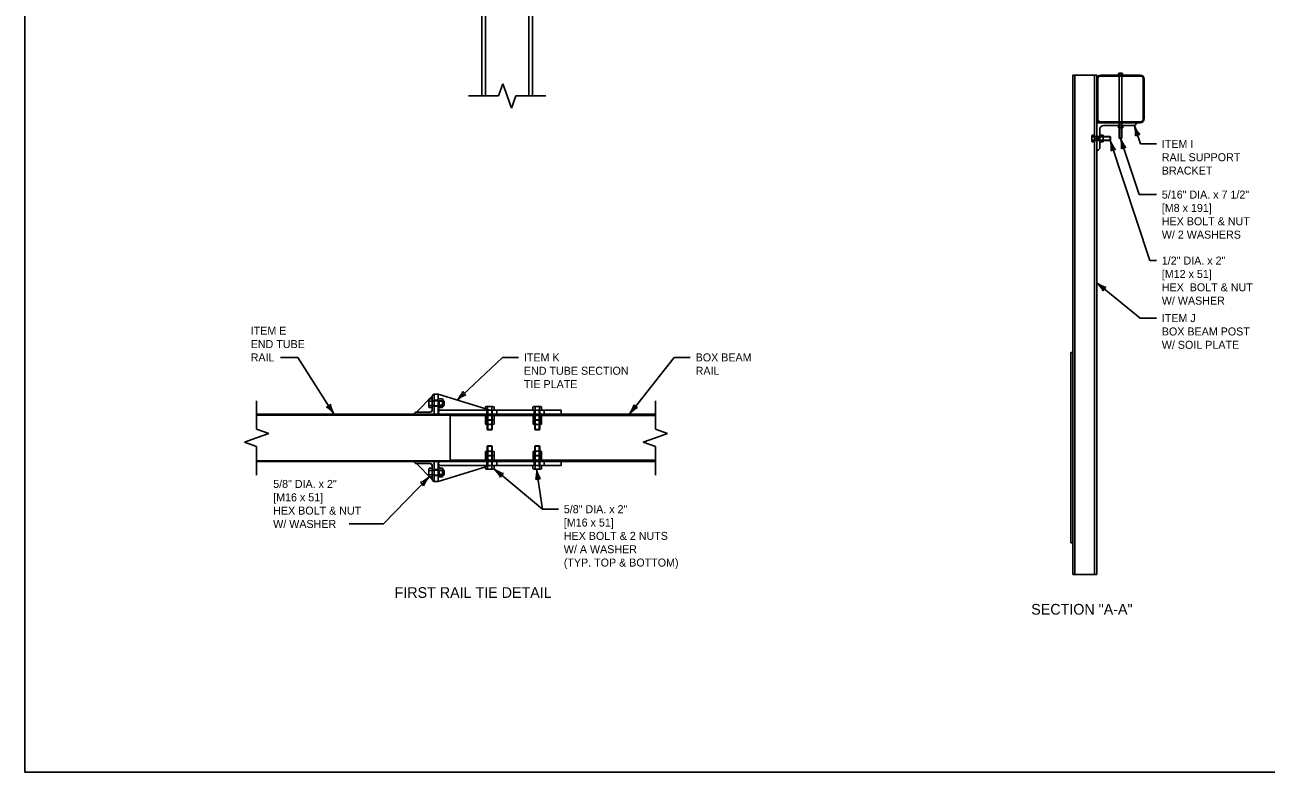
# Model space of a CAD drawing. Extents: x 49991.4 to 50021, y 49987.6 to 50011.4.
# Drawn here: x 49999.38 to 50008.69, y 49987.8 to 49993.4 of the extents above; entities that cross this region are included whole.
import ezdxf

# ---------------------------------------------------------------- set-up
doc = ezdxf.new("R2010")
doc.units = 0
for name, color, linetype in [('Level 1', 7, 'Continuous'), ('Level 2', 7, 'Continuous'), ('Level 3', 7, 'Continuous'), ('Level 4', 7, 'Continuous'), ('Level 6', 7, 'Continuous'), ('Level 63', 7, 'Continuous')]:
    doc.layers.add(name, color=color, linetype=linetype)

# ---------------------------------------------------------------- blocks, each defined once
blk = doc.blocks.new('HEX$NU')
at = {"layer": 'Level 63'}
for p, q in [((0, -0.32), (0, 0.32)), ((0.03, 0.43), (0.42, 0.43)), ((0.03, 0.22), (0.42, 0.22)), ((0.45, 0.32), (0.45, -0.32)), ((0.03, -0.22), (0.42, -0.22)), ((0.42, -0.43), (0.03, -0.43))]:
    blk.add_line(p, q, dxfattribs=at)
for centre, radius, start, end in [((0.21, 0.32), 0.21, 149.0201, 210.9799), ((0.8, 0), 0.796, 164.2217, 195.7782), ((0.24, 0.32), 0.21, 329.0201, 30.9799), ((-0.35, 0), 0.796, 344.2218, 15.7783), ((0.21, -0.32), 0.21, 149.0201, 210.9799), ((0.24, -0.32), 0.21, 329.0201, 30.9799)]:
    blk.add_arc(centre, radius, start, end, dxfattribs=at)

msp = doc.modelspace()

# ---------------------------------------------------------------- linework, layer by layer
at = {"layer": 'Level 1'}
for p, q in [((50003.1884, 49995.2856), (50003.1884, 49992.8668)), ((50002.8094, 49995.1742), (50002.8094, 49992.8668)), ((50002.8364, 49995.1742), (50002.8364, 49992.8668)), ((50003.1614, 49995.1742), (50003.1614, 49992.8668)), ((50007.241, 49993.0223), (50007.4192, 49993.0223)), ((50007.241, 49993.0223), (50007.241, 49990.9431)), ((50007.2564, 49993.0223), (50007.2564, 49989.2797)), ((50007.4038, 49993.0223), (50007.4038, 49989.2797)), ((50007.4192, 49993.0223), (50007.4192, 49989.2797)), ((50007.7459, 49993.0223), (50007.4489, 49993.0223)), ((50007.5854, 49993.0358), (50007.6095, 49993.0358)), ((50007.5894, 49993.0345), (50007.5894, 49993.0223)), ((50007.6055, 49993.0345), (50007.6055, 49993.0223)), ((50007.4266, 49992.9926), (50007.4266, 49992.6956)), ((50007.7459, 49993.0149), (50007.4489, 49993.0149)), ((50007.7682, 49992.6956), (50007.7682, 49992.9926)), ((50007.7756, 49992.6956), (50007.7756, 49992.9926)), ((50007.4192, 49992.6659), (50007.7162, 49992.6659)), ((50007.4489, 49992.6733), (50007.7459, 49992.6733)), ((50007.4489, 49992.6659), (50007.7459, 49992.6659)), ((50007.6067, 49992.6659), (50007.5881, 49992.6659)), ((50007.3821, 49992.5278), (50007.3821, 49992.5663)), ((50007.3842, 49992.5599), (50007.4038, 49992.5599)), ((50007.4415, 49992.6139), (50007.4415, 49992.4728)), ((50007.5196, 49992.5619), (50007.4681, 49992.5619)), ((50007.7014, 49992.6436), (50007.4712, 49992.6436)), ((50007.5196, 49992.5322), (50007.5196, 49992.5619)), ((50007.5196, 49992.5619), (50007.5226, 49992.5589)), ((50007.5226, 49992.5589), (50007.5226, 49992.5352)), ((50007.5881, 49992.5489), (50007.5881, 49992.6269)), ((50007.6067, 49992.6269), (50007.6067, 49992.5489)), ((50007.3842, 49992.5342), (50007.4038, 49992.5342)), ((50007.5196, 49992.5322), (50007.4681, 49992.5322)), ((50007.5196, 49992.5322), (50007.5226, 49992.5352)), ((50007.5881, 49992.5489), (50007.59, 49992.547)), ((50007.5881, 49992.5489), (50007.6067, 49992.5489)), ((50007.6049, 49992.547), (50007.59, 49992.547)), ((50007.6067, 49992.5489), (50007.6049, 49992.547)), ((50007.2261, 49990.9431), (50007.241, 49990.9431)), ((50007.2261, 49990.9431), (50007.2261, 49989.5173)), ((50007.241, 49990.9431), (50007.241, 49989.5173)), ((50002.4381, 49990.6157), (50002.3193, 49990.4969)), ((50002.4381, 49990.6157), (50002.4381, 49990.5117)), ((50002.453, 49990.482), (50002.453, 49990.6305)), ((50002.453, 49990.6305), (50002.4827, 49990.6305)), ((50002.4827, 49990.6305), (50002.4827, 49990.482)), ((50002.4827, 49990.6305), (50002.8725, 49990.5117)), ((50002.4111, 49990.5878), (50002.4111, 49990.5396)), ((50002.4137, 49990.5798), (50002.4381, 49990.5798)), ((50002.4137, 49990.5476), (50002.4381, 49990.5476)), ((50002.4233, 49990.4969), (50002.4381, 49990.5117)), ((50002.4827, 49990.5266), (50002.4975, 49990.5117)), ((50002.4975, 49990.5117), (50002.4827, 49990.4969)), ((50002.8725, 49990.5117), (50002.4975, 49990.5117)), ((50002.5235, 49990.5823), (50002.5161, 49990.5823)), ((50002.5161, 49990.5785), (50002.5235, 49990.5785)), ((50002.5235, 49990.5488), (50002.5161, 49990.5488)), ((50002.5161, 49990.5451), (50002.5235, 49990.5451)), ((50002.5235, 49990.5823), (50002.5235, 49990.5451)), ((50002.5235, 49990.5823), (50002.5272, 49990.5785)), ((50002.5235, 49990.5451), (50002.5272, 49990.5488)), ((50002.5272, 49990.5488), (50002.5272, 49990.5785)), ((50002.8367, 49990.5226), (50002.8367, 49990.5361)), ((50002.8447, 49990.5387), (50002.8929, 49990.5387)), ((50002.8527, 49990.5361), (50002.8527, 49990.5178)), ((50003.4035, 49990.5117), (50002.8725, 49990.5117)), ((50002.8849, 49990.5361), (50002.8849, 49990.5117)), ((50003.2012, 49990.5387), (50003.2494, 49990.5387)), ((50003.2092, 49990.5361), (50003.2092, 49990.5117)), ((50003.2413, 49990.5361), (50003.2413, 49990.5117)), ((50003.4035, 49990.5117), (50003.4035, 49990.482)), ((50001.121, 49990.482), (50002.5718, 49990.482)), ((50002.3193, 49990.4969), (50002.4233, 49990.4969)), ((50002.4975, 49990.482), (50002.4827, 49990.4969)), ((50002.5718, 49990.482), (50002.5718, 49990.1256)), ((50002.5718, 49990.482), (50004.1107, 49990.482)), ((50001.121, 49990.1256), (50002.5718, 49990.1256)), ((50002.3193, 49990.1107), (50002.4233, 49990.1107)), ((50002.4381, 49989.9919), (50002.3193, 49990.1107)), ((50002.4111, 49990.0198), (50002.4111, 49990.068)), ((50002.4137, 49990.06), (50002.4381, 49990.06)), ((50002.4233, 49990.1107), (50002.4381, 49990.0959)), ((50002.4381, 49989.9919), (50002.4381, 49990.0959)), ((50002.453, 49990.1256), (50002.453, 49989.9771)), ((50002.453, 49990.1107), (50002.453, 49989.9771)), ((50002.4975, 49990.1256), (50002.4827, 49990.1107)), ((50002.4827, 49989.9771), (50002.4827, 49990.1256)), ((50002.4975, 49990.0959), (50002.4827, 49990.1107)), ((50002.4827, 49990.081), (50002.4975, 49990.0959)), ((50002.4827, 49989.9771), (50002.8725, 49990.0959)), ((50002.8725, 49990.0959), (50002.4975, 49990.0959)), ((50002.5161, 49990.0624), (50002.5235, 49990.0624)), ((50002.5235, 49990.0587), (50002.5161, 49990.0587)), ((50002.5235, 49990.0253), (50002.5235, 49990.0624)), ((50002.5235, 49990.0624), (50002.5272, 49990.0587)), ((50002.5272, 49990.0587), (50002.5272, 49990.029)), ((50002.5718, 49990.1256), (50004.1107, 49990.1256)), ((50002.8367, 49990.0849), (50002.8367, 49990.0714)), ((50002.8447, 49990.0688), (50002.8929, 49990.0688)), ((50002.8527, 49990.0714), (50002.8527, 49990.0898)), ((50003.4035, 49990.0959), (50002.8725, 49990.0959)), ((50002.8849, 49990.0714), (50002.8849, 49990.0959)), ((50003.2012, 49990.0688), (50003.2494, 49990.0688)), ((50003.2092, 49990.0714), (50003.2092, 49990.0959)), ((50003.2413, 49990.0714), (50003.2413, 49990.0959)), ((50003.4035, 49990.0959), (50003.4035, 49990.1256)), ((50002.4137, 49990.0278), (50002.4381, 49990.0278)), ((50002.453, 49989.9771), (50002.4827, 49989.9771)), ((50002.5161, 49990.029), (50002.5235, 49990.029)), ((50002.5235, 49990.0253), (50002.5161, 49990.0253)), ((50002.5235, 49990.0253), (50002.5272, 49990.029)), ((50007.2261, 49989.5173), (50007.241, 49989.5173)), ((50007.241, 49989.5173), (50007.241, 49989.2797)), ((50007.241, 49989.2797), (50007.4192, 49989.2797))]:
    msp.add_line(p, q, dxfattribs=at)
msp.add_lwpolyline([(49999.3835, 49998.9992), (50016.7501, 49998.9992), (50016.7501, 49987.7988), (49999.3835, 49987.7988)], close=True, dxfattribs=at)
for points in [[(50007.6135, 49993.0345), (50007.6135, 49993.0223), (50007.5813, 49993.0223), (50007.5813, 49993.0345)], [(50007.3842, 49992.5728), (50007.4038, 49992.5728), (50007.4038, 49992.5213), (50007.3842, 49992.5213)], [(50002.4137, 49990.5315), (50002.4381, 49990.5315), (50002.4381, 49990.5959), (50002.4137, 49990.5959)], [(50002.901, 49990.5361), (50002.901, 49990.5117), (50002.8725, 49990.5117)], [(50003.2574, 49990.5361), (50003.2574, 49990.5117), (50003.1931, 49990.5117), (50003.1931, 49990.5361)], [(50002.4137, 49990.076), (50002.4381, 49990.076), (50002.4381, 49990.0117), (50002.4137, 49990.0117)], [(50002.901, 49990.0714), (50002.901, 49990.0959), (50002.8725, 49990.0959)], [(50003.2574, 49990.0714), (50003.2574, 49990.0959), (50003.1931, 49990.0959), (50003.1931, 49990.0714)]]:
    msp.add_lwpolyline(points, dxfattribs=at)
for centre, radius, start, end in [((50007.4489, 49992.9926), 0.0297, 90, 180), ((50007.5854, 49993.029), 0.00687, 54.1654, 125.8346), ((50007.5974, 49993.0103), 0.0255, 71.6338, 108.3662), ((50007.6095, 49993.029), 0.00687, 54.1655, 125.8345), ((50007.7459, 49992.9926), 0.0297, 0, 90), ((50007.4489, 49992.9926), 0.0223, 90, 180), ((50007.7459, 49992.9926), 0.0223, 0, 90), ((50007.4489, 49992.6956), 0.0297, 180, 270), ((50007.4489, 49992.6956), 0.0223, 180, 270), ((50007.6935, 49992.6649), 0.0228, 290.31325, 2.31193), ((50007.7459, 49992.6956), 0.0297, 270, 0), ((50007.7459, 49992.6956), 0.0223, 270, 0), ((50007.3931, 49992.5663), 0.011, 144.1655, 215.8345), ((50007.423, 49992.547), 0.0408, 161.6338, 198.3662), ((50007.4712, 49992.6139), 0.0297, 90, 180), ((50007.3931, 49992.5278), 0.011, 144.1654, 215.8346), ((50007.4201, 49992.4807), 0.0228, 267.68839, 339.69174), ((50002.453, 49990.6157), 0.0149, 90, 180), ((50002.4248, 49990.5878), 0.0137, 144.1654, 215.8346), ((50002.4621, 49990.5637), 0.051, 161.6338, 198.3662), ((50002.4248, 49990.5396), 0.0137, 144.1655, 215.8345), ((50002.4233, 49990.5117), 0.0149, 270, 0), ((50002.8447, 49990.525), 0.0137, 54.1654, 125.8346), ((50002.8688, 49990.4877), 0.051, 71.6338, 108.3662), ((50002.8929, 49990.525), 0.0137, 54.1655, 125.8345), ((50003.2012, 49990.525), 0.0137, 54.1654, 125.8346), ((50003.2253, 49990.4877), 0.051, 71.6338, 108.3662), ((50003.2494, 49990.525), 0.0137, 54.1655, 125.8345), ((50002.3193, 49990.482), 0.0149, 90, 180), ((50002.3193, 49990.1256), 0.0149, 180, 270), ((50002.4248, 49990.068), 0.0137, 144.1655, 215.8345), ((50002.4621, 49990.0439), 0.051, 161.6338, 198.3662), ((50002.4233, 49990.0959), 0.0149, 0, 90), ((50002.8447, 49990.0826), 0.0137, 234.1654, 305.8346), ((50002.8688, 49990.1199), 0.051, 251.6338, 288.3662), ((50002.8929, 49990.0826), 0.0137, 234.17005, 305.83905), ((50003.2012, 49990.0826), 0.0137, 234.1654, 305.8346), ((50003.2253, 49990.1199), 0.051, 251.6338, 288.3662), ((50003.2494, 49990.0826), 0.0137, 234.1655, 305.8345), ((50002.4248, 49990.0198), 0.0137, 144.16573, 215.83493), ((50002.453, 49989.9919), 0.0149, 180, 270)]:
    msp.add_arc(centre, radius, start, end, dxfattribs=at)
at = {"layer": 'Level 3'}
for p, q in [((50007.7014, 49992.6436), (50007.7467, 49992.5068)), ((50007.5196, 49992.5322), (50007.818, 49991.6323)), ((50007.5974, 49992.547), (50007.7367, 49992.127)), ((50007.7467, 49992.5068), (50007.8671, 49992.5068)), ((50007.7367, 49992.127), (50007.8671, 49992.127)), ((50007.8671, 49991.6323), (50007.818, 49991.6323)), ((50007.4192, 49991.4663), (50007.744, 49991.2012)), ((50007.744, 49991.2012), (50007.8671, 49991.2012)), ((50001.301, 49990.9069), (50001.4312, 49990.9069)), ((50001.4312, 49990.9069), (50001.7011, 49990.482)), ((50002.9649, 49990.9069), (50002.6235, 49990.5876)), ((50003.0849, 49990.9069), (50002.9649, 49990.9069)), ((50003.9167, 49990.482), (50004.2526, 49990.9069)), ((50004.3726, 49990.9069), (50004.2526, 49990.9069)), ((50002.901, 49990.0714), (50003.2641, 49989.7694)), ((50003.2641, 49989.7694), (50003.2196, 49990.0688)), ((50002.4137, 49990.0117), (50002.0723, 49989.6587)), ((50003.3841, 49989.7694), (50003.2641, 49989.7694)), ((50001.8141, 49989.6587), (50002.0723, 49989.6587))]:
    msp.add_line(p, q, dxfattribs=at)
for centre, radius, start, end in [((50007.4877, 49992.5824), 0.2223, 355.80283, 15.98634), ((50007.9187, 49992.7277), 0.233, 201.17413, 220.42398), ((50007.7417, 49992.5219), 0.0548, 90.48564, 126.208), ((50007.3059, 49992.471), 0.2223, 355.80283, 15.98634), ((50007.7369, 49992.6164), 0.233, 201.17413, 220.42398), ((50007.56, 49992.4105), 0.0548, 90.48564, 126.208), ((50007.3837, 49992.4858), 0.2223, 355.80283, 15.98634), ((50007.8147, 49992.6312), 0.233, 201.17413, 220.42398), ((50007.6378, 49992.4253), 0.0548, 90.48564, 126.208), ((50007.2716, 49991.3001), 0.2223, 28.23292, 48.41643), ((50007.5575, 49991.6539), 0.233, 233.60422, 252.85407), ((50007.5185, 49991.3853), 0.0548, 122.91573, 158.63809), ((50002.4562, 49990.7497), 0.233, 315.90483, 335.15468), ((50002.7685, 49990.4191), 0.2223, 110.53353, 130.71704), ((50002.7172, 49990.6752), 0.0548, 205.21634, 240.9387), ((50001.6324, 49990.5902), 0.0548, 284.56938, 320.29174), ((50001.5109, 49990.3475), 0.233, 35.25788, 54.50773), ((50001.8935, 49990.5934), 0.2223, 189.88658, 210.07008), ((50003.727, 49990.6173), 0.233, 324.49453, 343.74438), ((50004.0852, 49990.3371), 0.2223, 119.12323, 139.30674), ((50003.9962, 49990.5826), 0.0548, 213.80604, 249.5284), ((50002.7519, 49989.9065), 0.2223, 27.70004, 47.88354), ((50003.041, 49990.2577), 0.233, 233.07134, 252.32119), ((50002.9985, 49990.0452), 0.2223, 345.91481, 6.09832), ((50003.4481, 49990.1144), 0.233, 191.28611, 210.53596), ((50002.2604, 49990.1727), 0.2223, 293.41516, 313.59867), ((50002.3246, 49989.9196), 0.0548, 28.09797, 63.82033), ((50002.589, 49989.8582), 0.233, 138.78646, 158.03631), ((50002.9995, 49989.9894), 0.0548, 122.38284, 158.10521), ((50003.2384, 49989.942), 0.0548, 80.59762, 116.31998)]:
    msp.add_arc(centre, radius, start, end, dxfattribs=at)
at = {"layer": 'Level 4'}
for p, q in [((50007.5863, 49993.0149), (50007.5863, 49993.0223)), ((50007.5881, 49993.0149), (50007.5881, 49993.0223)), ((50007.6067, 49993.0149), (50007.6067, 49993.0223)), ((50007.6086, 49993.0149), (50007.6086, 49993.0223)), ((50007.5881, 49992.6733), (50007.5881, 49993.0149)), ((50007.6067, 49993.0149), (50007.6067, 49992.6733)), ((50007.5863, 49992.6733), (50007.5863, 49992.6659)), ((50007.5881, 49992.6269), (50007.5881, 49992.6733)), ((50007.59, 49992.6659), (50007.59, 49992.6274)), ((50007.6049, 49992.6274), (50007.6049, 49992.6659)), ((50007.6067, 49992.6269), (50007.6067, 49992.6733)), ((50007.6086, 49992.6733), (50007.6086, 49992.6659)), ((50007.4038, 49992.5619), (50007.4681, 49992.5619)), ((50007.4335, 49992.5619), (50007.4335, 49992.5322)), ((50007.4685, 49992.5589), (50007.4335, 49992.5589)), ((50007.5196, 49992.5589), (50007.4685, 49992.5589)), ((50007.5196, 49992.5322), (50007.5196, 49992.5619)), ((50007.59, 49992.6274), (50007.59, 49992.5489)), ((50007.6049, 49992.5489), (50007.6049, 49992.6274)), ((50007.4192, 49992.547), (50007.4038, 49992.547)), ((50007.4681, 49992.5322), (50007.4038, 49992.5322)), ((50007.4335, 49992.5352), (50007.4685, 49992.5352)), ((50007.4685, 49992.5352), (50007.5196, 49992.5352)), ((50007.5881, 49992.5489), (50007.6067, 49992.5489)), ((50002.5161, 49990.5823), (50002.4381, 49990.5823)), ((50002.4381, 49990.5451), (50002.5161, 49990.5451)), ((50002.453, 49990.586), (50002.4827, 49990.586)), ((50002.453, 49990.5414), (50002.4827, 49990.5414)), ((50002.4901, 49990.5451), (50002.4901, 49990.5823)), ((50002.4901, 49990.5785), (50002.5161, 49990.5785)), ((50002.5161, 49990.5488), (50002.4901, 49990.5488)), ((50002.8367, 49990.5226), (50002.8367, 49990.5117)), ((50002.8466, 49990.482), (50002.8466, 49990.5117)), ((50002.8503, 49990.3669), (50002.8503, 49990.5117)), ((50002.8527, 49990.5178), (50002.8527, 49990.5117)), ((50002.854, 49990.5117), (50002.854, 49990.3669)), ((50002.8837, 49990.3669), (50002.8837, 49990.5117)), ((50002.8874, 49990.5117), (50002.8874, 49990.3669)), ((50002.9208, 49990.482), (50002.9208, 49990.5117)), ((50003.203, 49990.5117), (50003.203, 49990.482)), ((50003.2067, 49990.3669), (50003.2067, 49990.5117)), ((50003.2104, 49990.5117), (50003.2104, 49990.3669)), ((50003.2401, 49990.3669), (50003.2401, 49990.5117)), ((50003.2438, 49990.5117), (50003.2438, 49990.3669)), ((50003.2773, 49990.5117), (50003.2773, 49990.482)), ((50001.121, 49990.4746), (50002.5718, 49990.4746)), ((50002.5718, 49990.4709), (50004.1107, 49990.4709)), ((50002.8428, 49990.482), (50002.8428, 49990.4709)), ((50002.8948, 49990.482), (50002.8948, 49990.4709)), ((50003.1993, 49990.482), (50003.1993, 49990.4709)), ((50003.2513, 49990.482), (50003.2513, 49990.4709)), ((50002.8503, 49990.3669), (50002.8874, 49990.3669)), ((50002.8503, 49990.3669), (50002.854, 49990.3632)), ((50002.8837, 49990.3632), (50002.854, 49990.3632)), ((50002.8874, 49990.3669), (50002.8837, 49990.3632)), ((50003.2067, 49990.3669), (50003.2438, 49990.3669)), ((50003.2067, 49990.3669), (50003.2104, 49990.3632)), ((50003.2401, 49990.3632), (50003.2104, 49990.3632)), ((50003.2438, 49990.3669), (50003.2401, 49990.3632)), ((50002.8503, 49990.2407), (50002.854, 49990.2444)), ((50002.8503, 49990.2407), (50002.8503, 49990.0959)), ((50002.8503, 49990.2407), (50002.8874, 49990.2407)), ((50002.8837, 49990.2444), (50002.854, 49990.2444)), ((50002.854, 49990.0959), (50002.854, 49990.2407)), ((50002.8874, 49990.2407), (50002.8837, 49990.2444)), ((50002.8837, 49990.2407), (50002.8837, 49990.0959)), ((50002.8874, 49990.0959), (50002.8874, 49990.2407)), ((50003.2067, 49990.2407), (50003.2104, 49990.2444)), ((50003.2067, 49990.2407), (50003.2438, 49990.2407)), ((50003.2067, 49990.2407), (50003.2067, 49990.0959)), ((50003.2401, 49990.2444), (50003.2104, 49990.2444)), ((50003.2104, 49990.0959), (50003.2104, 49990.2407)), ((50003.2438, 49990.2407), (50003.2401, 49990.2444)), ((50003.2401, 49990.2407), (50003.2401, 49990.0959)), ((50003.2438, 49990.0959), (50003.2438, 49990.2407)), ((50002.5718, 49990.1367), (50004.1107, 49990.1367)), ((50002.8428, 49990.1256), (50002.8428, 49990.1367)), ((50002.8948, 49990.1256), (50002.8948, 49990.1367)), ((50003.1993, 49990.1256), (50003.1993, 49990.1367)), ((50003.2513, 49990.1256), (50003.2513, 49990.1367)), ((50001.121, 49990.133), (50002.5718, 49990.133)), ((50002.4381, 49990.0624), (50002.5161, 49990.0624)), ((50002.453, 49990.0662), (50002.4827, 49990.0662)), ((50002.4901, 49990.0624), (50002.4901, 49990.0253)), ((50002.5161, 49990.0587), (50002.4901, 49990.0587)), ((50002.8367, 49990.0849), (50002.8367, 49990.0959)), ((50002.8466, 49990.1256), (50002.8466, 49990.0959)), ((50002.8527, 49990.0898), (50002.8527, 49990.0959)), ((50002.9208, 49990.1256), (50002.9208, 49990.0959)), ((50003.203, 49990.0959), (50003.203, 49990.1256)), ((50003.2773, 49990.0959), (50003.2773, 49990.1256)), ((50002.5161, 49990.0253), (50002.4381, 49990.0253)), ((50002.453, 49990.0216), (50002.4827, 49990.0216)), ((50002.4901, 49990.029), (50002.5161, 49990.029))]:
    msp.add_line(p, q, dxfattribs=at)
at = {"layer": 'Level 6'}
for p, q in [((50002.9664, 49992.9581), (50002.934, 49992.8667)), ((50002.9664, 49992.9581), (50002.9988, 49992.8667)), ((50002.934, 49992.8667), (50002.7094, 49992.8667)), ((50002.9988, 49992.8667), (50003.0312, 49992.7753)), ((50003.0636, 49992.8667), (50003.0312, 49992.7753)), ((50003.2884, 49992.8667), (50003.0636, 49992.8667)), ((50001.121, 49990.3686), (50001.121, 49990.582)), ((50004.1107, 49990.3686), (50004.1107, 49990.582)), ((50001.2124, 49990.3362), (50001.121, 49990.3686)), ((50001.2124, 49990.3362), (50001.121, 49990.3038)), ((50004.2021, 49990.3362), (50004.1107, 49990.3686)), ((50004.2021, 49990.3362), (50004.1107, 49990.3038)), ((50001.121, 49990.3038), (50001.0296, 49990.2714)), ((50001.121, 49990.239), (50001.0296, 49990.2714)), ((50001.121, 49990.0256), (50001.121, 49990.239)), ((50004.1107, 49990.3038), (50004.0193, 49990.2714)), ((50004.1107, 49990.239), (50004.0193, 49990.2714)), ((50004.1107, 49990.0256), (50004.1107, 49990.239))]:
    msp.add_line(p, q, dxfattribs=at)

# ---------------------------------------------------------------- block references
at = {"layer": 'Level 1', "xscale": 0.059406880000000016, "yscale": 0.059406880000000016}
msp.add_blockref('HEX$NU', (50007.4415, 49992.5476), dxfattribs=at)
at = {"layer": 'Level 1'}
for p, xscale, yscale, rotation in [((50007.5979, 49992.6269), 0.03712930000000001, 0.03712930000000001, 90), ((50002.5161, 49990.5644), 0.07425860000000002, 0.07425860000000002, 180), ((50002.5161, 49990.0445), 0.07425860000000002, -0.07425860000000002, 180)]:
    msp.add_blockref('HEX$NU', p, dxfattribs=dict(at, xscale=xscale, yscale=yscale, rotation=rotation))
at = {"layer": 'Level 4', "xscale": 0.07425860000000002}
for p, yscale, rotation in [((50002.869, 49990.4716), 0.07425860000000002, -90.00000000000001), ((50002.869, 49990.438), 0.07425860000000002, -90.00000000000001), ((50003.2255, 49990.4716), 0.07425860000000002, -90.00000000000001), ((50003.2255, 49990.438), 0.07425860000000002, -90.00000000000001), ((50002.869, 49990.1701), -0.07425860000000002, 89.99999999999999), ((50002.869, 49990.1375), -0.07425860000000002, 89.99999999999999), ((50003.2255, 49990.1701), -0.07425860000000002, 89.99999999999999), ((50003.2255, 49990.1375), -0.07425860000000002, 89.99999999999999)]:
    msp.add_blockref('HEX$NU', p, dxfattribs=dict(at, yscale=yscale, rotation=rotation))

# ---------------------------------------------------------------- texts
at = {"layer": 'Level 2'}
for s, height, p in [('ITEM I', 0.06, (50007.9072, 49992.4768)), ('RAIL SUPPORT ', 0.06, (50007.9072, 49992.3768)), ('BRACKET', 0.06, (50007.9072, 49992.2768)), ('5/16" DIA. x 7 1/2"', 0.06, (50007.9072, 49992.097)), ('[M8 x 191]', 0.06, (50007.9072, 49991.997)), ('HEX BOLT & NUT', 0.06, (50007.9072, 49991.897)), ('W/ 2 WASHERS', 0.06, (50007.9072, 49991.797)), ('1/2" DIA. x 2"', 0.06, (50007.9072, 49991.6023)), ('[M12 x 51]', 0.06, (50007.9072, 49991.5023)), ('HEX  BOLT & NUT ', 0.06, (50007.9072, 49991.4023)), ('W/ WASHER', 0.06, (50007.9072, 49991.3023)), ('ITEM J', 0.06, (50007.9072, 49991.1712)), ('ITEM E', 0.06, (50001.077, 49991.0769)), ('BOX BEAM POST', 0.06, (50007.9072, 49991.0712)), ('END TUBE', 0.06, (50001.077, 49990.9769)), ('W/ SOIL PLATE', 0.06, (50007.9072, 49990.9712)), ('RAIL', 0.06, (50001.077, 49990.8769)), ('ITEM K ', 0.06, (50003.1249, 49990.8769)), ('BOX BEAM', 0.06, (50004.4126, 49990.8769)), ('END TUBE SECTION', 0.06, (50003.1249, 49990.7769)), ('RAIL', 0.06, (50004.4126, 49990.7769)), ('TIE PLATE', 0.06, (50003.1249, 49990.6769)), ('5/8" DIA. x 2"', 0.06, (50001.2454, 49989.9287)), ('[M16 x 51]', 0.06, (50001.2454, 49989.8287)), ('HEX BOLT & NUT', 0.06, (50001.2454, 49989.7287)), ('5/8" DIA. x 2"', 0.06, (50003.4241, 49989.7394)), ('W/ WASHER', 0.06, (50001.2454, 49989.6287)), ('[M16 x 51]', 0.06, (50003.4241, 49989.6394)), ('HEX BOLT & 2 NUTS', 0.06, (50003.4241, 49989.5394)), ('W/ A WASHER', 0.06, (50003.4241, 49989.4394)), ('(TYP. TOP & BOTTOM)', 0.06, (50003.4241, 49989.3394)), ('FIRST RAIL TIE DETAIL', 0.08, (50002.1558, 49989.1049)), ('SECTION "A-A"', 0.08, (50006.9285, 49988.9795))]:
    msp.add_text(s, height=height, dxfattribs=at).set_placement(p)

doc.saveas('drawing.dxf')
